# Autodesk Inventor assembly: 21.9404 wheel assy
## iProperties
Created: 2010-10
Part Number: 21.9404 wheel assy
Document SubType Name: Assembly
Designer: Administrator
Mass: 248.42 g
Surface Area: 409.073 cm^2
Volume: 154.86 cm^3
Density: 1.60416 g/cm^3
Author: Administrator
